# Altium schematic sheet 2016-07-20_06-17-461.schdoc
size 212 x 129 mm; SheetNumber: 1; SheetTotal: 1
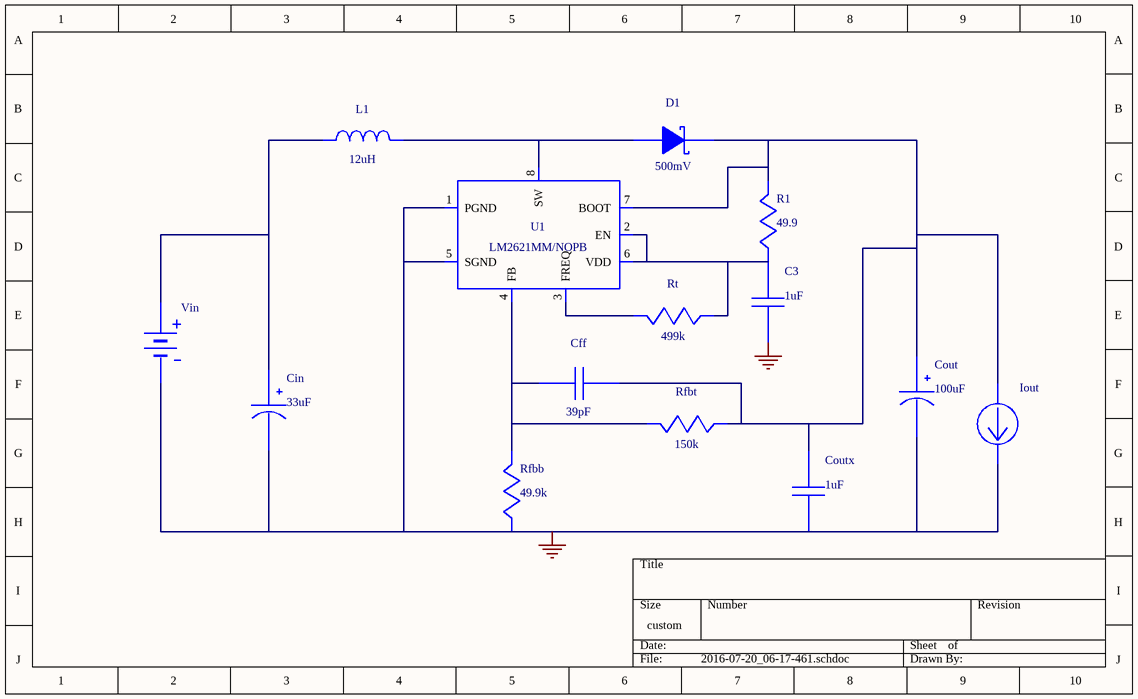
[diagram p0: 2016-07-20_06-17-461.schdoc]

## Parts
C3  value 1uF  (hidden comment: EMK212B7105KG-T)
Cff  value 39pF  (hidden comment: CC0805JRNPO9BN390)
Cin  value 33uF  (hidden comment: 293D336X9016C2TE3)
Cout  value 100uF  (hidden comment: 593D107X0010D2TE3)
Coutx  value 1uF  (hidden comment: C0603C105Z9VACTU)
D1  value 500mV  (hidden comment: B320A-13-F)
Iout  WB_CURRENT_LOAD  (value not drawn)
L1  value 12uH  (hidden comment: SRR1260-120M)
R1  value 49.9  (hidden comment: CRCW040249R9FKED)
Rfbb  value 49.9k  (hidden comment: CRCW040249K9FKED)
Rfbt  value 150k  (hidden comment: CRCW0402150KFKED)
Rt  value 499k  (hidden comment: CRCW0402499KFKED)
U1  LM2621MM/NOPB
Vin  WB_BATTERY  (value not drawn)

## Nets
0: C3.2 Cin.2(-) Cout.2(-) Coutx.2 Iout.2(-) Rfbb.2 U1.1(PGND) U1.5(SGND) Vin.2(-)
NetC3_1: C3.1 R1.2 Rt.2 U1.2(EN) U1.6(VDD)
NetCff_1: Cff.1 Cout.1(+) Coutx.1 D1.1(K) Iout.1(+) R1.1 Rfbt.2 U1.7(BOOT)
NetCff_2: Cff.2 Rfbb.1 Rfbt.1 U1.4(FB)
NetCin_1: Cin.1(+) L1.1 Vin.1(+)
NetD1_2: D1.2(A) L1.2 U1.8(SW)
NetRt_1: Rt.1 U1.3(FREQ)

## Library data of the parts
C3 = EMK212B7105KG-T: Manufacturer Name: Taiyo Yuden
Cff = CC0805JRNPO9BN390: CC0805JRNPO9BN39; Manufacturer Name: Yageo America
Cin = 293D336X9016C2TE3: 293D336X9016C2TE; Manufacturer Name: Vishay-Sprague
Cout = 593D107X0010D2TE3: 593D107X0010D2TE; Manufacturer Name: Vishay-Sprague
Coutx = C0603C105Z9VACTU: Manufacturer Name: Kemet
D1 = B320A-13-F: Manufacturer Name: Diodes Inc.
L1 = SRR1260-120M: Manufacturer Name: Bourns
R1 = CRCW040249R9FKED: Manufacturer Name: Vishay-Dale
Rfbb = CRCW040249K9FKED: Manufacturer Name: Vishay-Dale
Rfbt = CRCW0402150KFKED: Manufacturer Name: Vishay-Dale
Rt = CRCW0402499KFKED: Manufacturer Name: Vishay-Dale
U1 = LM2621MM/NOPB: Manufacturer Name: Texas Instruments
